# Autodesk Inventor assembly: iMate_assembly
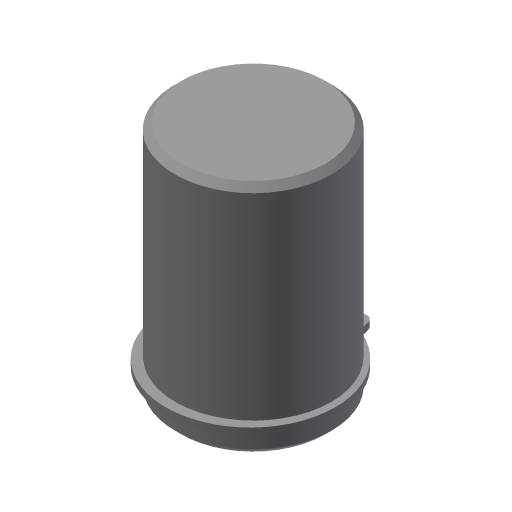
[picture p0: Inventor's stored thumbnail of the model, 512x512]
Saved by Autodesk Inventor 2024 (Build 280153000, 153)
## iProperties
Created: 2016-08
Part Number: iMate_assembly
Document SubType Name: Assembly
Designer: Sandeep
Author: Sandeep
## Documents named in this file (3)
- D:\PROJECTS\Project 2023\RESOURCES INVENTOR 2024\RESOURCES INVENTOR 2024\Inventor_2024_tut\Inventor_2024_tut\c17_Inv_2024_tut\c17_tut02\iMate_assembly.iam
- D:\PROJECTS\Project 2023\RESOURCES INVENTOR 2024\RESOURCES INVENTOR 2024\Inventor_2024_tut\Inventor_2024_tut\c17_Inv_2024_tut\c17_tut02\Shaft.ipt
- D:\PROJECTS\Project 2023\RESOURCES INVENTOR 2024\RESOURCES INVENTOR 2024\Inventor_2024_tut\Inventor_2024_tut\c17_Inv_2024_tut\c17_tut02\circlip.ipt
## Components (2 placed, 2 different names)
1. Shaft:1
2. circlip:1
